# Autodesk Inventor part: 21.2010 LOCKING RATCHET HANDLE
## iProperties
Created: 2007-01
Part Number: 21.2010 LOCKING RATCHET HANDLE
Document SubType Name: Modeling
Designer: Andy Moles
Density: 1 g/cm^3
Author: Andy Moles
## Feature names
1. Base1
2. Chamfer1
